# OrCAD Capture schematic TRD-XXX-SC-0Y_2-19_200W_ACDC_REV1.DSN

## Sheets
1 4: size A3
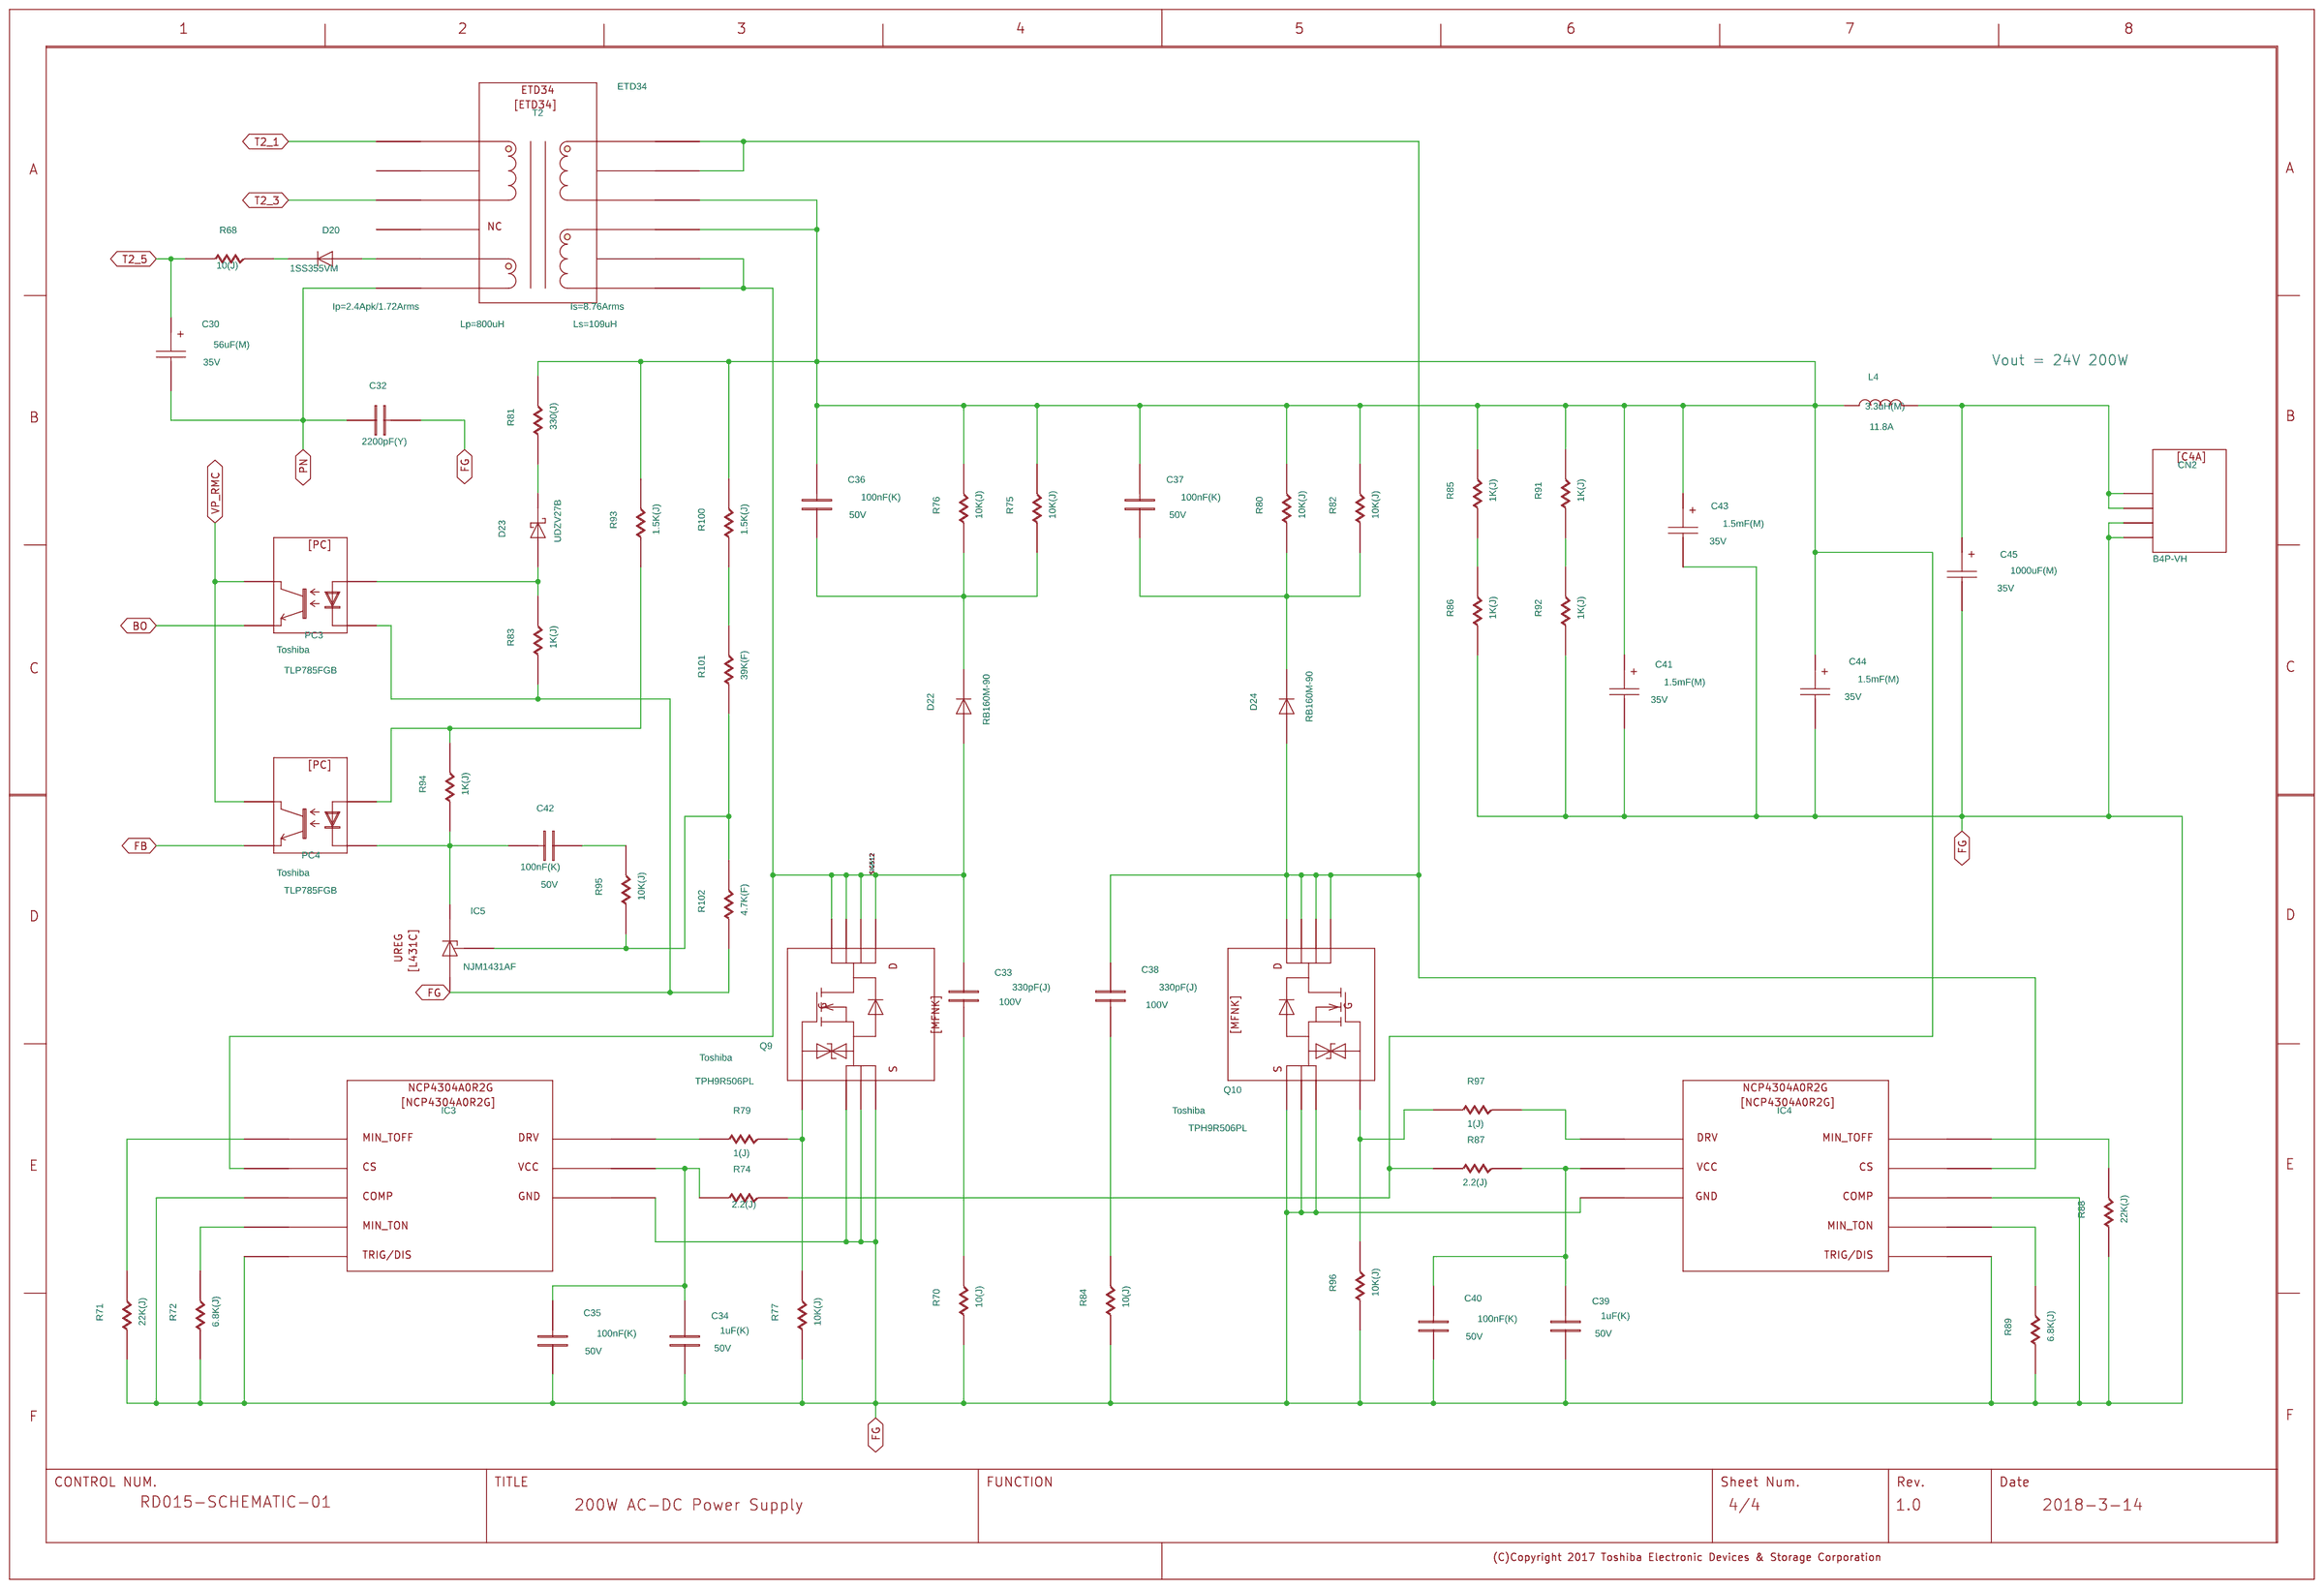
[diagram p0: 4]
2 3: size A3
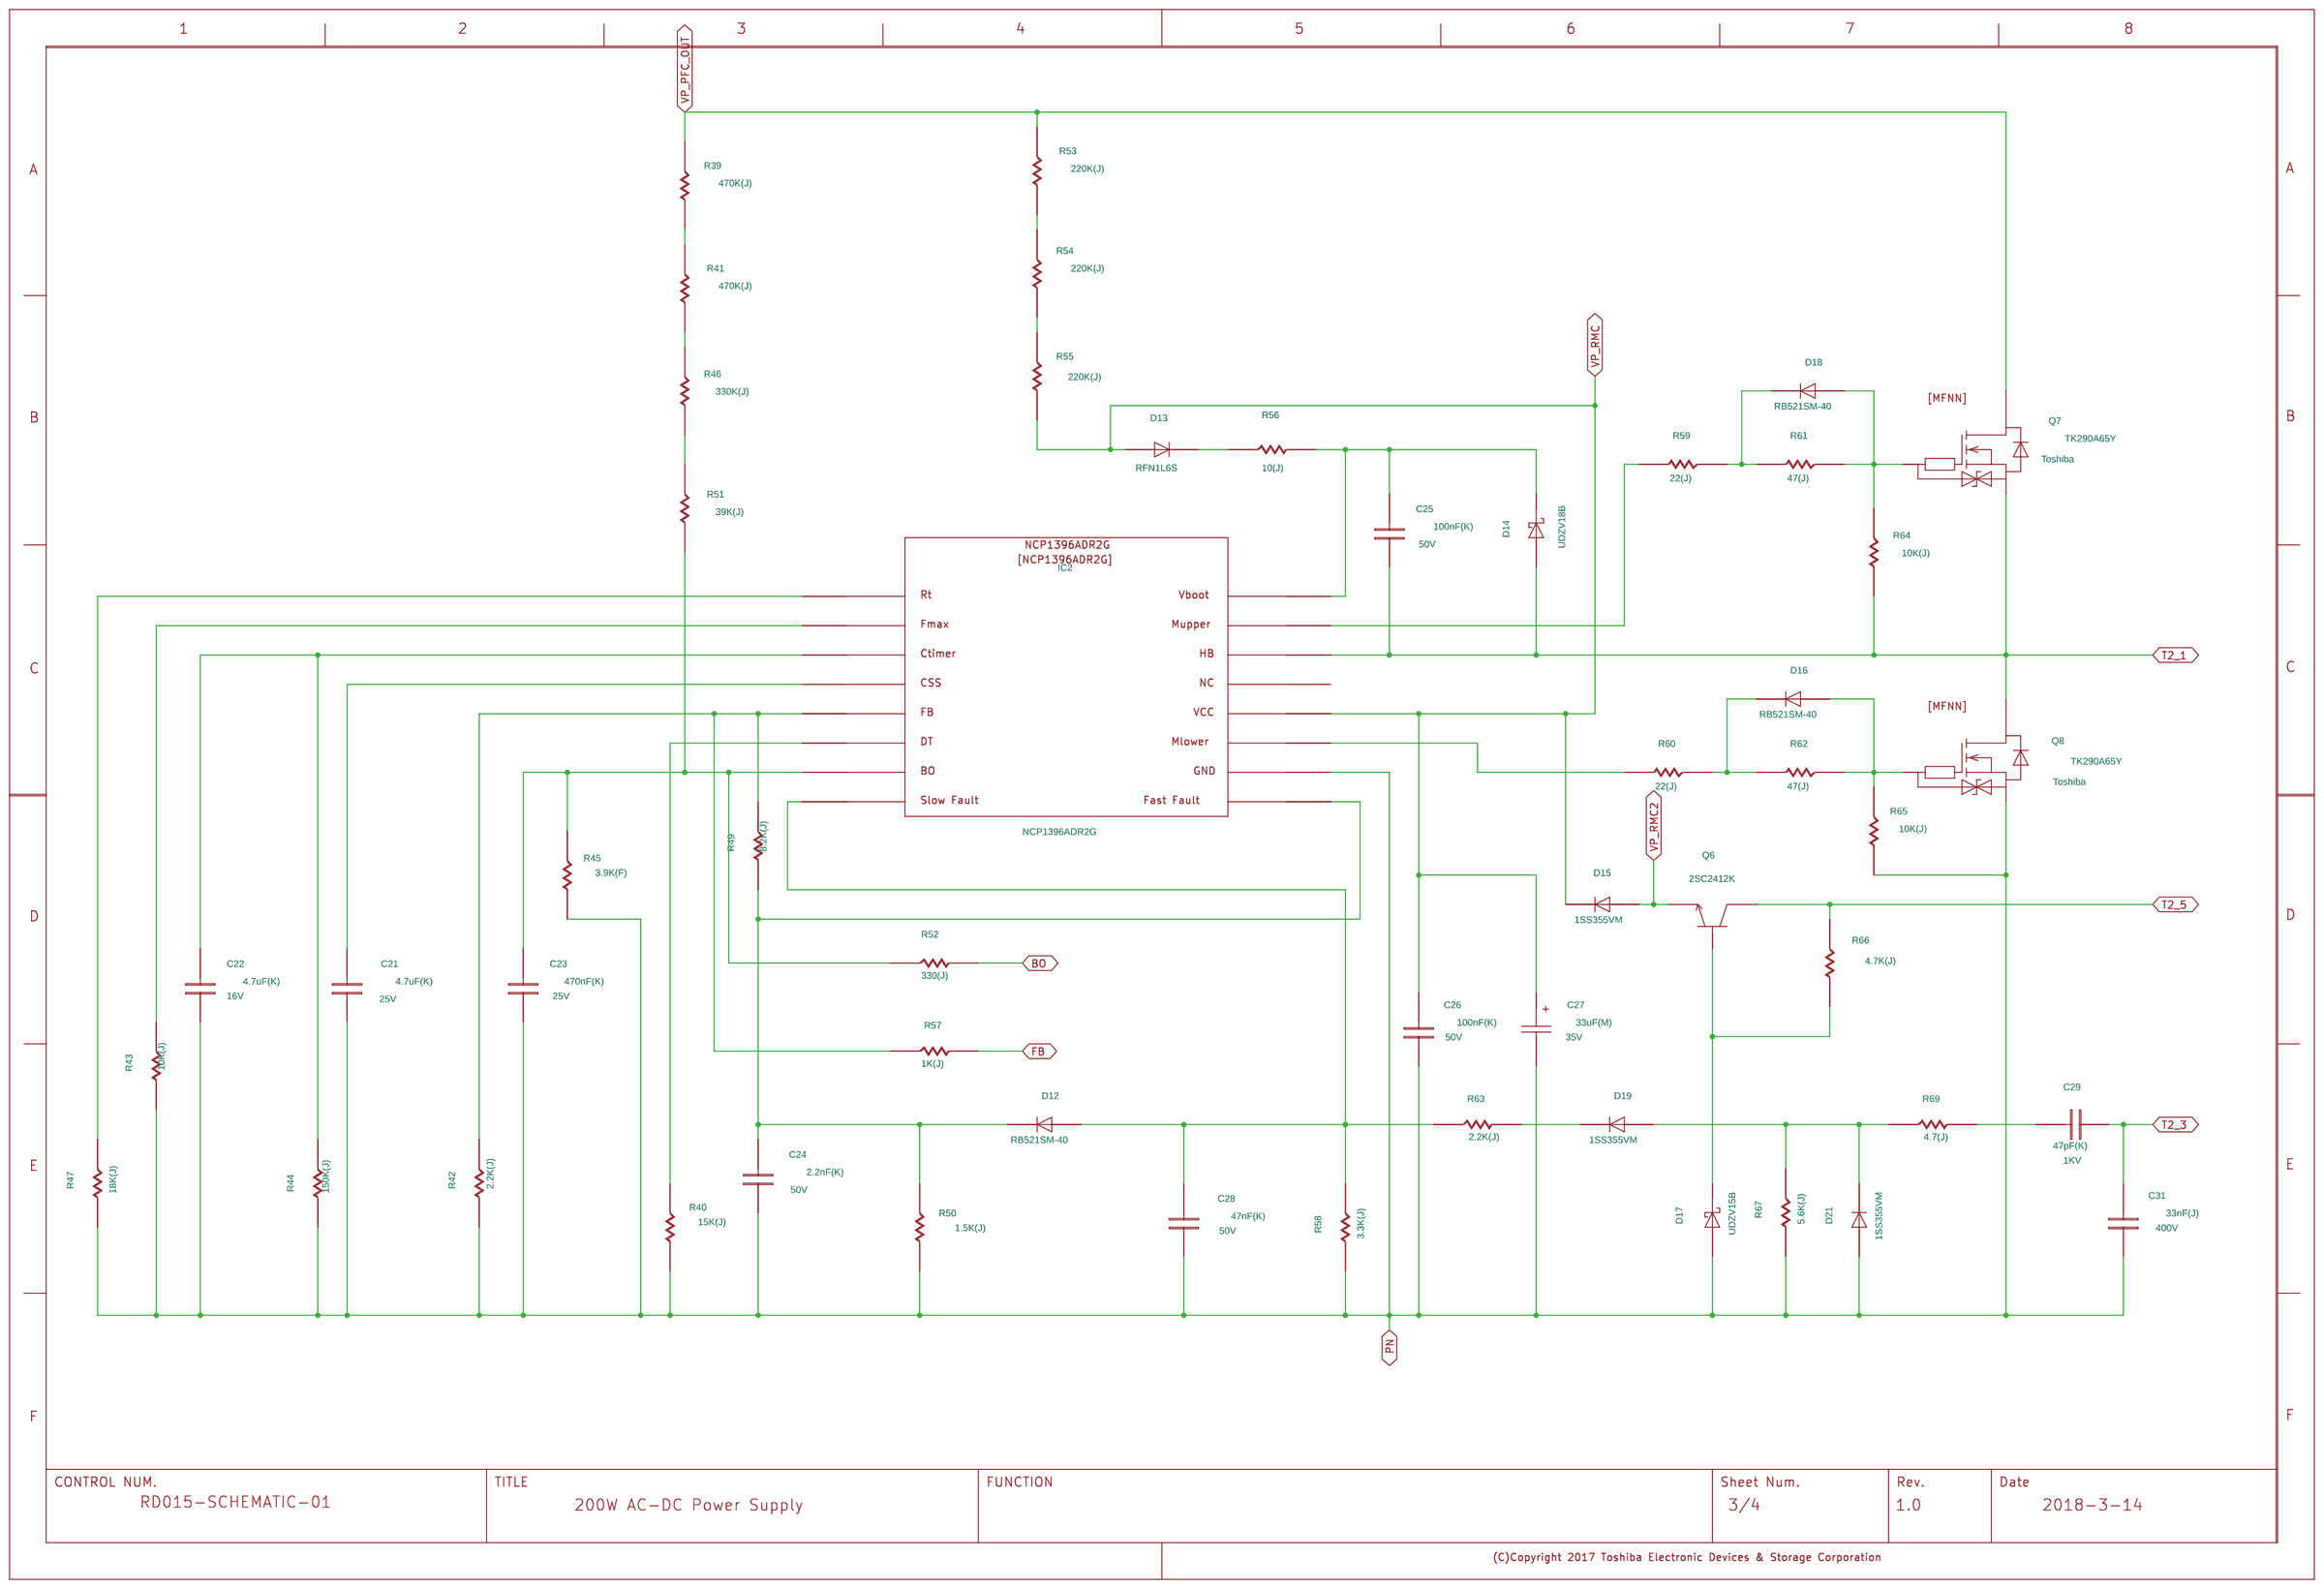
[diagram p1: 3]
3 2: size A3
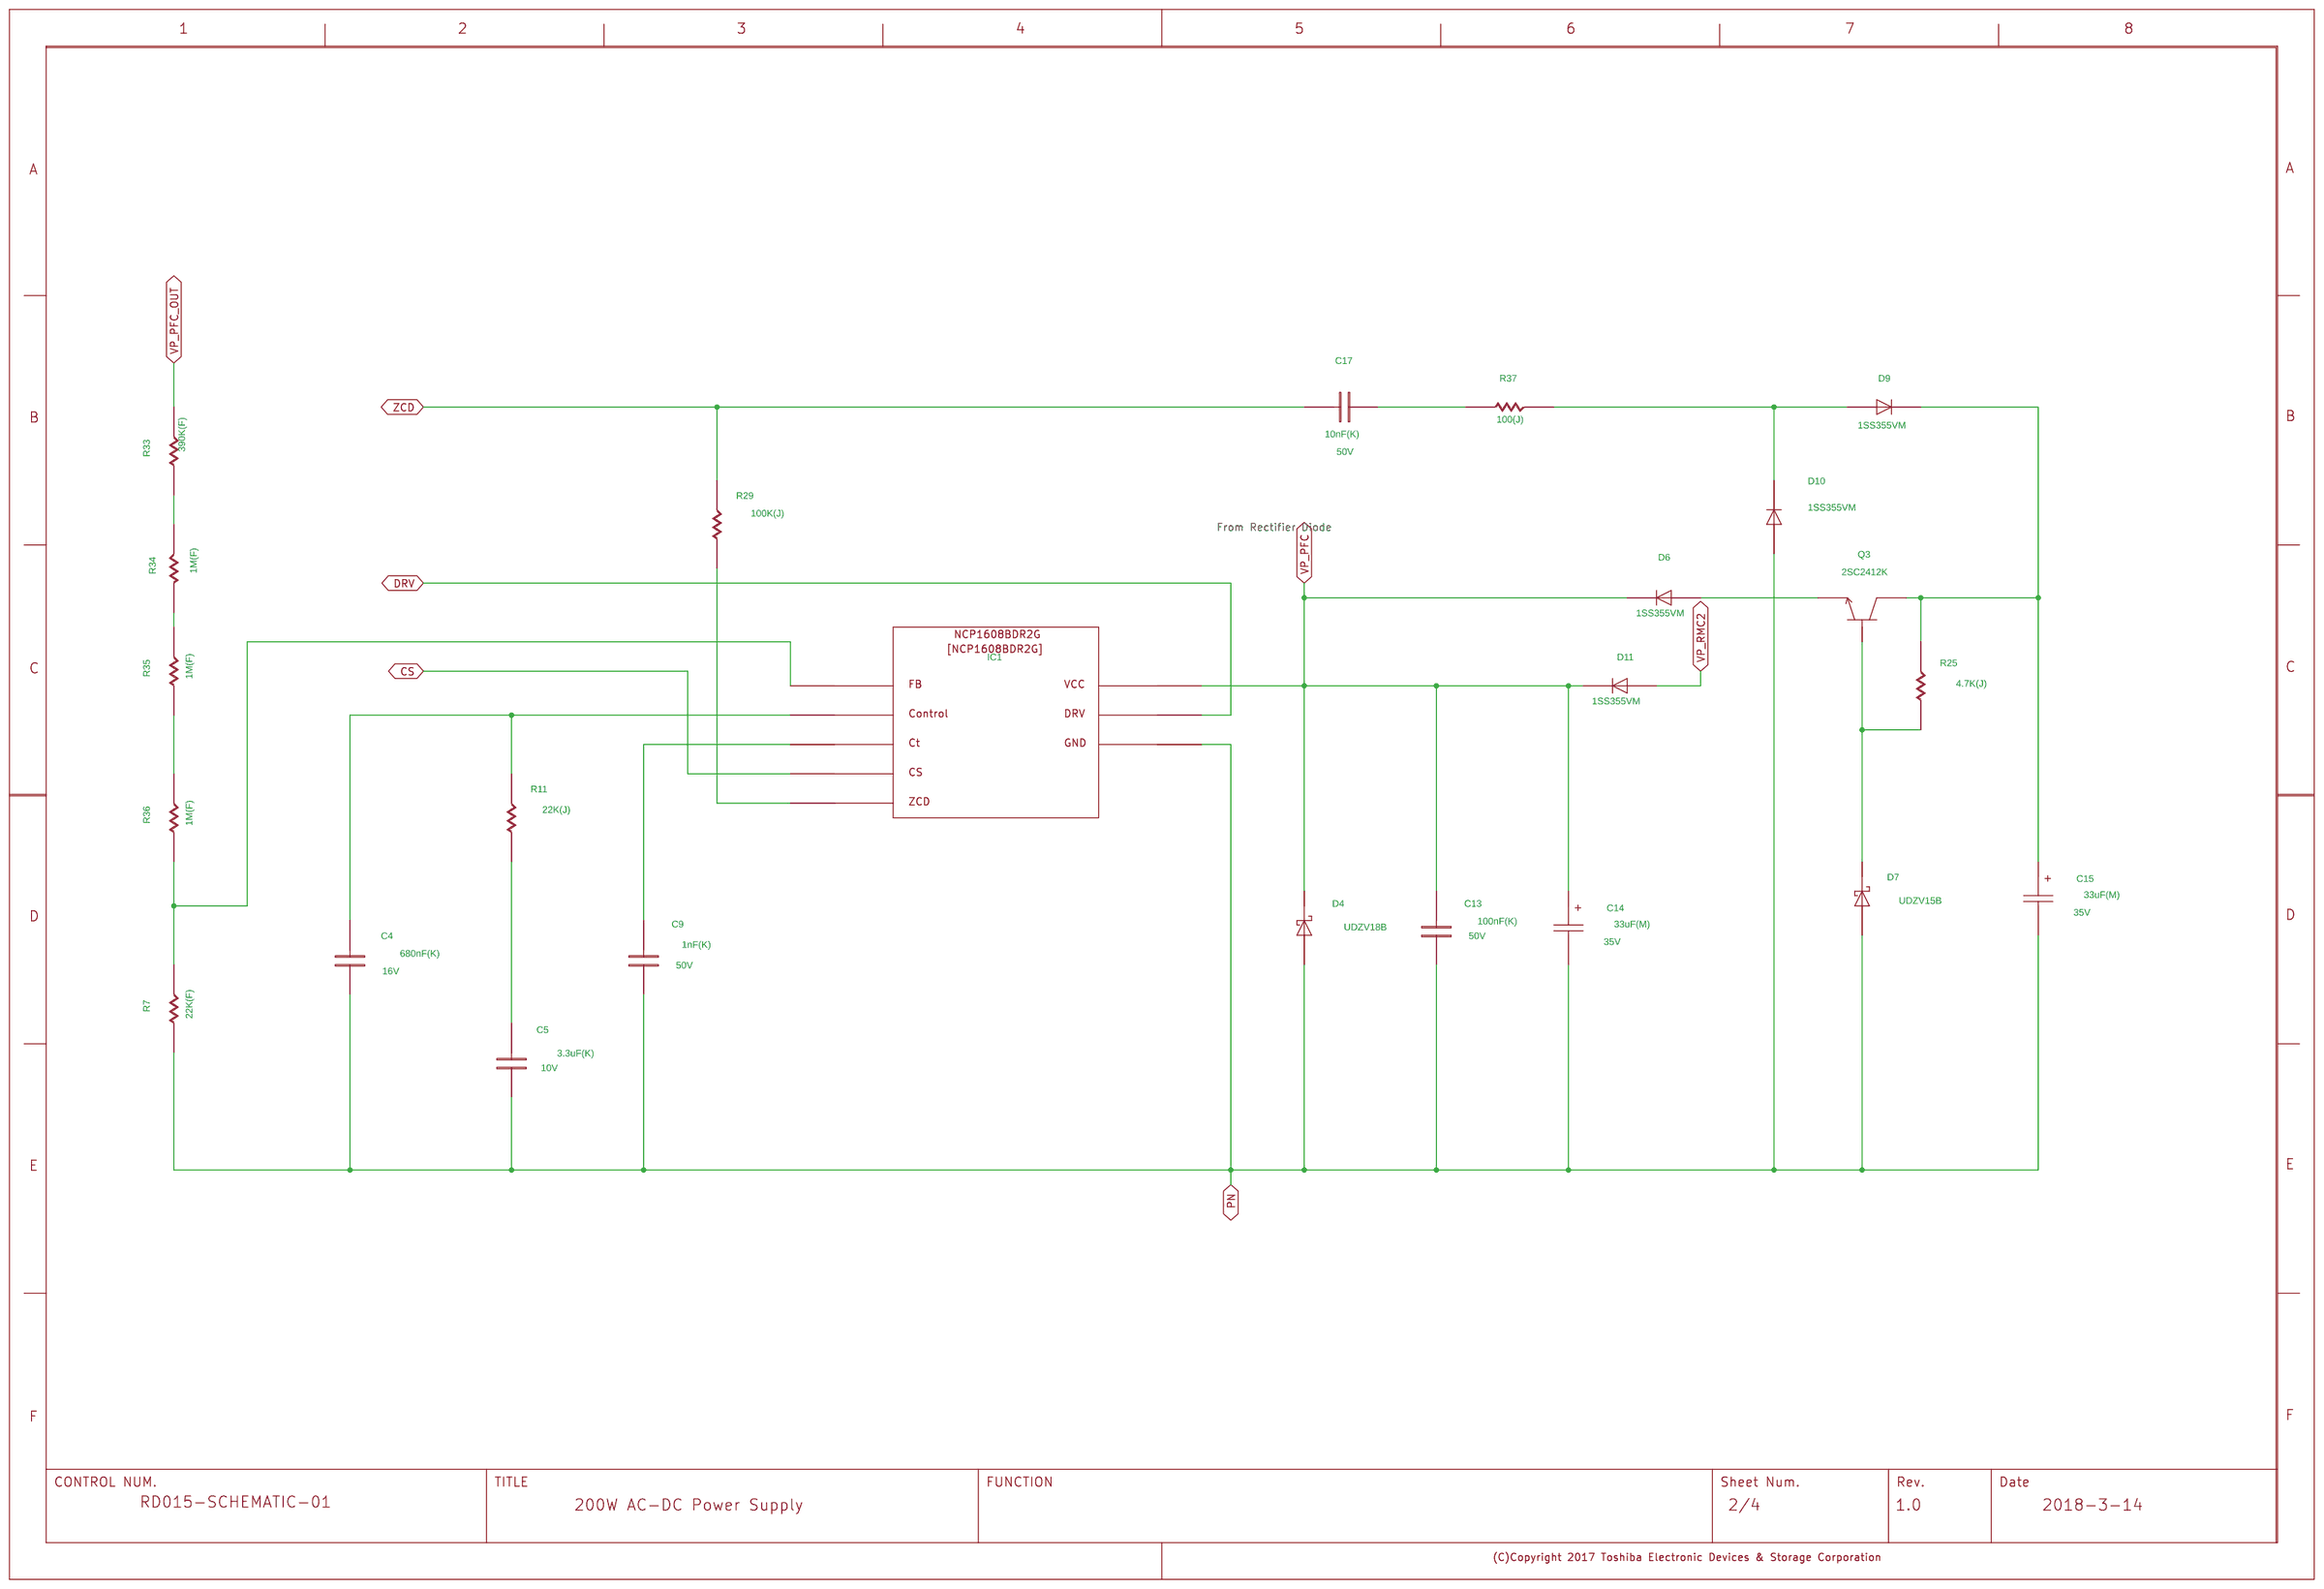
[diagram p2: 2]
4 1: size A3
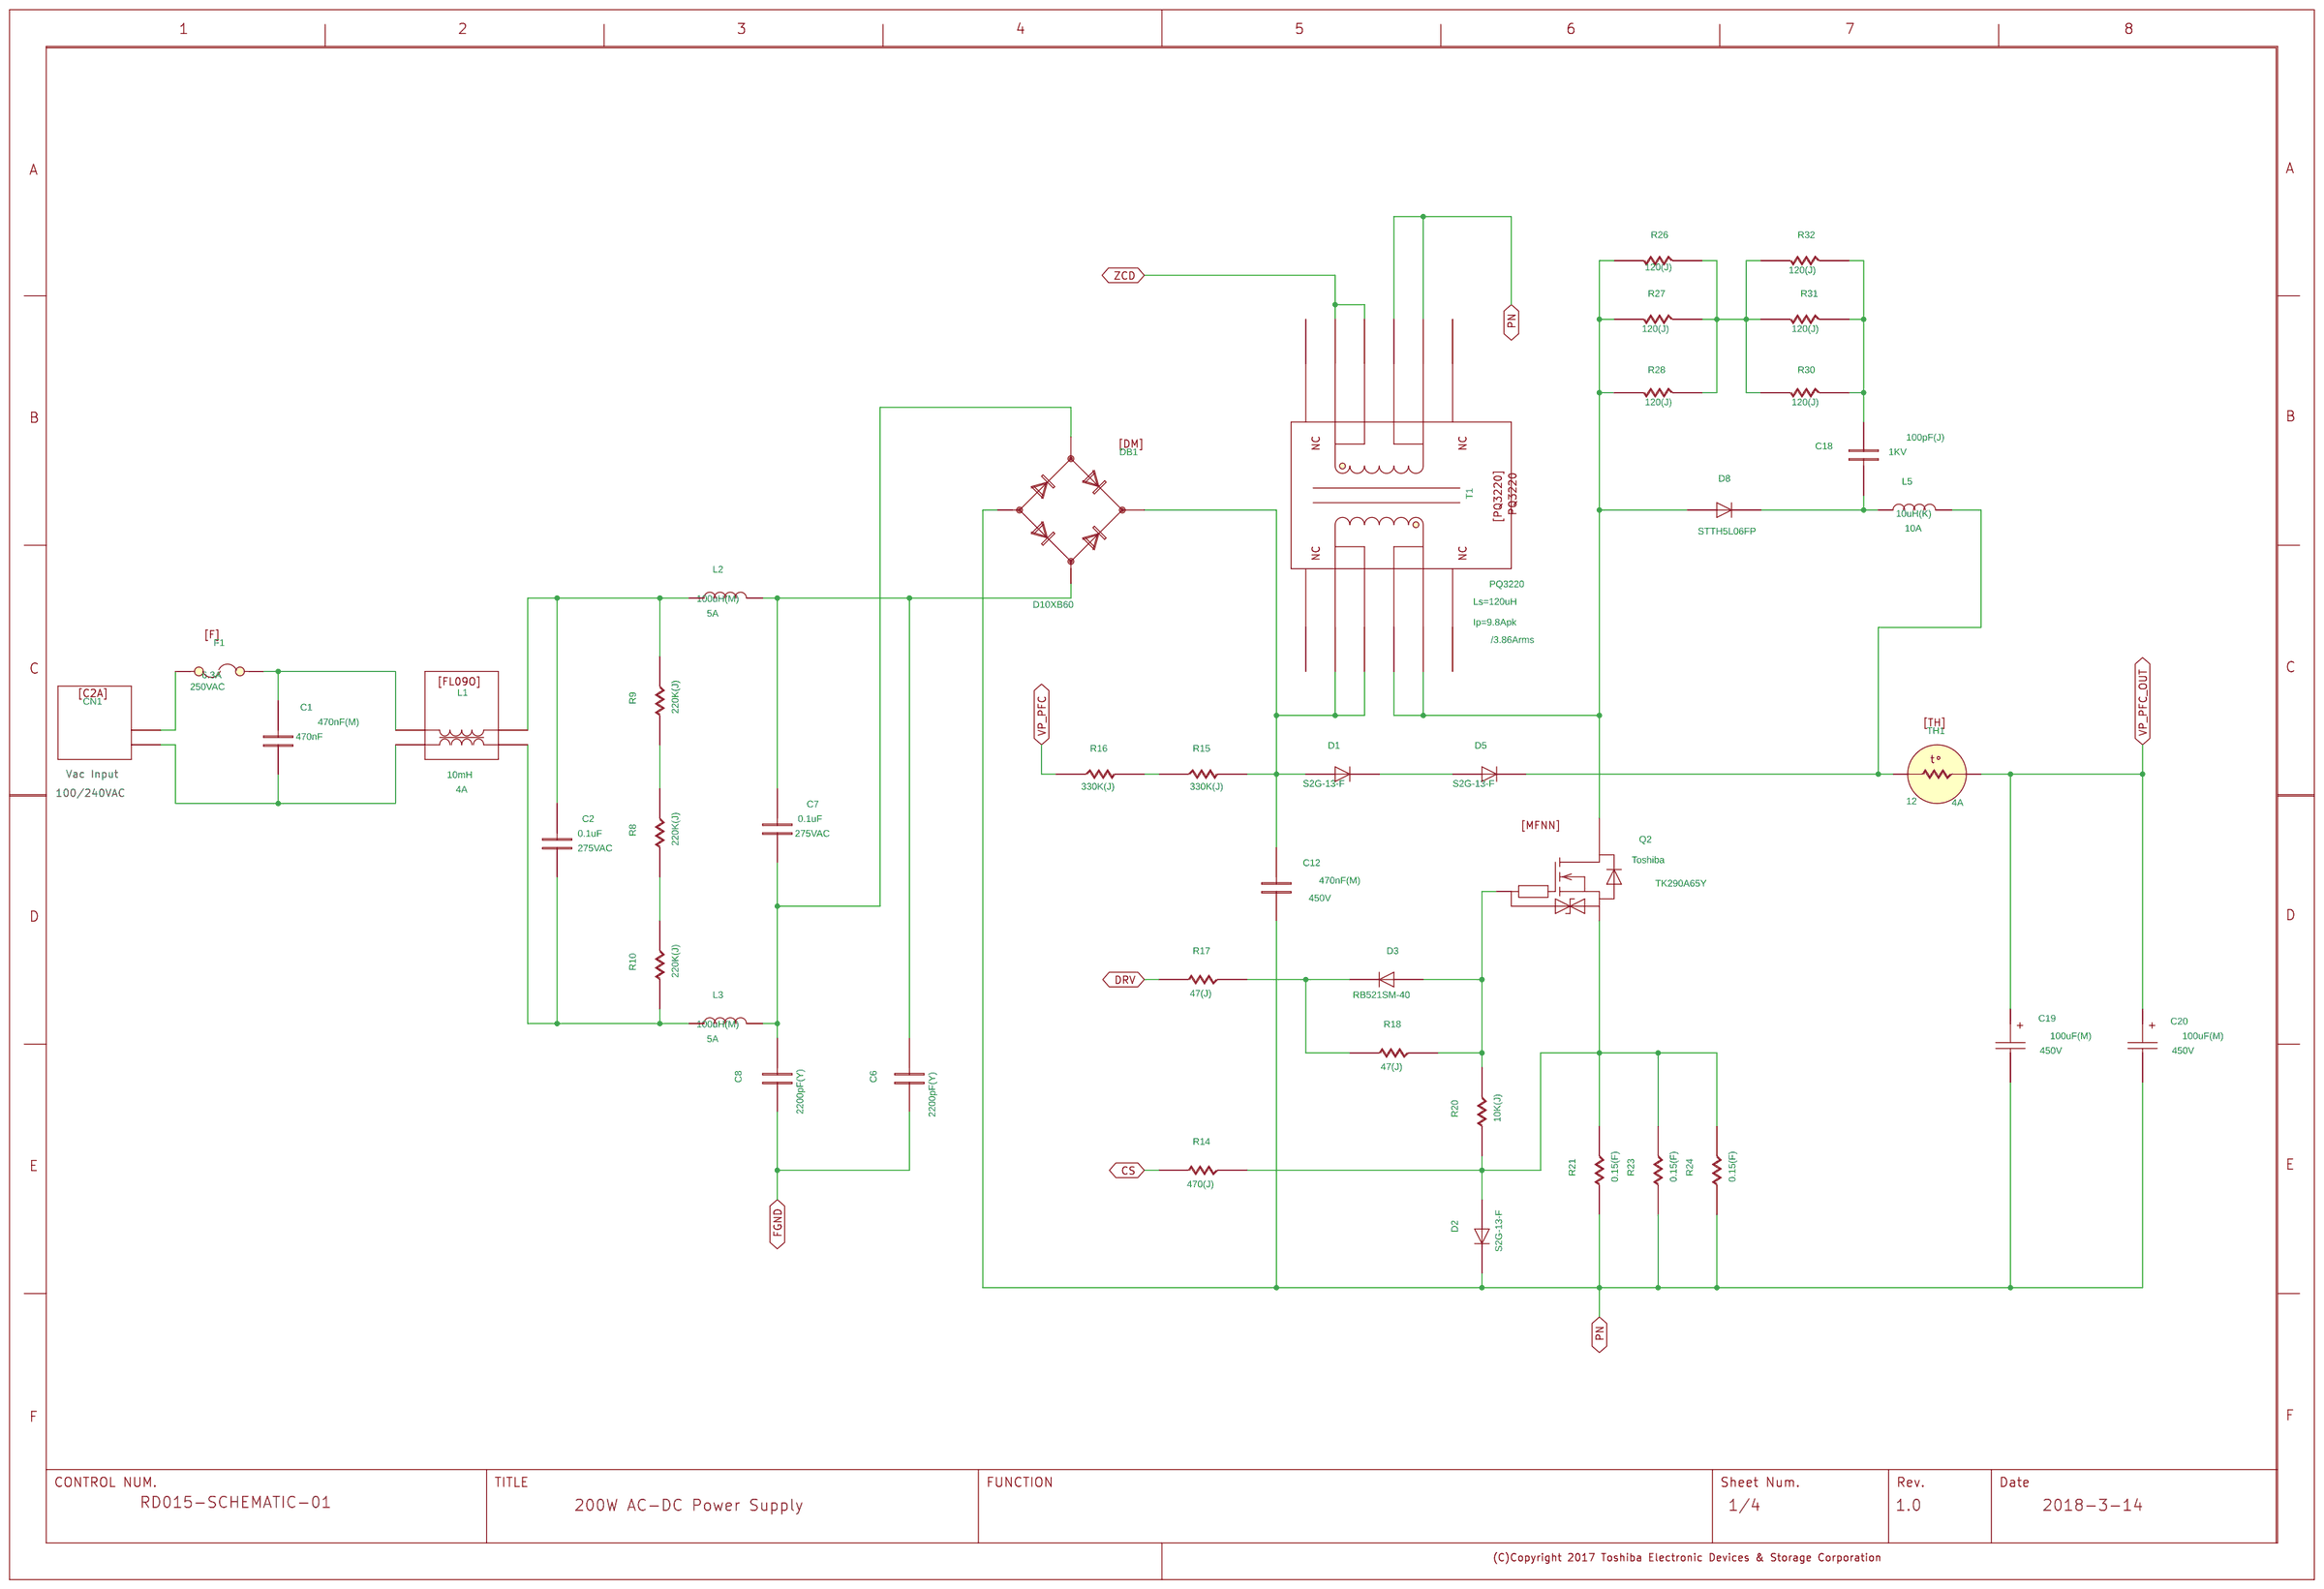
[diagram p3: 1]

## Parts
sheet 1
C1  C  [DIP]
C2  C  [DIP]
C6  C  [DIP]
C7  C  [DIP]
C8  C  [DIP]
C12  C  [DIP]
C18  C  [DIP]
C19  CP  [DIP]
C20  CP  [DIP]
CN1  C2A
D1  D  [SMB]
D2  D  [SMB]
D3  D  [EMD2]
D5  D  [SMB]
D8  D  [TO-220FPAC]
DB1  DM  [SIP]
F1  F  [DIP]
L1  FL09O  [DIP]
L2  L  [DIP]
L3  L  [DIP]
L5  L  [DIP]
Q2  MFNN  [TO-220SIS]
R8  R  [3216]
R9  R  [3216]
R10  R  [3216]
R14  R  [1608]
R15  R  [3216]
R16  R  [3216]
R17  R  [3216]
R18  R  [3216]
R20  R  [1608]
R21  R  [3226]
R23  R  [3226]
R24  R  [3226]
R26  R  [3216]
R27  R  [3216]
R28  R  [3216]
R30  R  [3216]
R31  R  [3216]
R32  R  [3216]
T1  S-PQ3220  [DIP]
TH1  TH  [DIP]
U?#3  WAKU_DEF100
sheet 2
C4  C  [2012]
C5  C  [3216]
C9  C  [1608]
C13  C  [1608]
C14  CP  [DIP]
C15  CP  [DIP]
C17  C  [1608]
D4  SBD  [UMD2]
D6  D  [UMD2]
D7  SBD  [UMD2]
D9  D  [UMD2]
D10  D  [UMD2]
D11  D  [UMD2]
IC1  S-NCP1608BDR2G  [SOIC]
Q3  TRN  [SOT-346]
R7  R  [1608]
R11  R  [1608]
R25  R  [1608]
R29  R  [1608]
R33  R  [1608]
R34  R  [1608]
R35  R  [1608]
R36  R  [1608]
R37  R  [3216]
U?#2  WAKU_DEF100
sheet 3
C21  C  [3216]
C22  C  [3216]
C23  C  [2012]
C24  C  [1608]
C25  C  [1608]
C26  C  [1608]
C27  CP  [DIP]
C28  C  [1608]
C29  C  [3216]
C31  C  [DIP]
D12  D  [EMD2]
D13  D  [PMDS]
D14  SBD  [UMD2]
D15  D  [UMD2]
D16  D  [EMD2]
D17  SBD  [UMD2]
D18  D  [EMD2]
D19  D  [UMD2]
D21  D  [UMD2]
IC2  S-NCP1396ADR2G  [SOIC]
Q6  TRN  [SOT-346]
Q7  MFNN  [TO-346]
Q8  MFNN  [TO-346]
R39  R  [3216]
R40  R  [1608]
R41  R  [3216]
R42  R  [1608]
R43  R  [1608]
R44  R  [1608]
R45  R  [1608]
R46  R  [3216]
R47  R  [1608]
R49  R  [1608]
R50  R  [1608]
R51  R  [1608]
R52  R  [1608]
R53  R  [3216]
R54  R  [3216]
R55  R  [3216]
R56  R  [1608]
R57  R  [1608]
R58  R  [1608]
R59  R  [3216]
R60  R  [3216]
R61  R  [3216]
R62  R  [3216]
R63  R  [1608]
R64  R  [1608]
R65  R  [1608]
R66  R  [1608]
R67  R  [1608]
R69  R  [1608]
U?#1  WAKU_DEF100
sheet 4
C30  CP  [DIP]
C32  C  [DIP]
C33  C  [1608]
C34  C  [3216]
C35  C  [1608]
C36  C  [1608]
C37  C  [1608]
C38  C  [1608]
C39  C  [3216]
C40  C  [1608]
C41  CP  [DIP]
C42  C  [1608]
C43  CP  [DIP]
C44  CP  [DIP]
C45  CP  [DIP]
CN2  C4A
D20  D  [UMD2]
D22  D  [PMDU]
D23  SBD  [UMD2]
D24  D  [PMDU]
IC3  S-NCP4304A0R2G  [SOIC]
IC4  S-NCP4304A0R2G  [SOIC]
IC5  L431C  [SOT-23]
L4  L  [DIP]
PC3  PC  [DIP4]
PC4  PC  [DIP4]
Q9  MFNK  [SOP Advance]
Q10  MFNK  [SOP Advance]
R68  R  [1608]
R70  R  [3216]
R71  R  [1608]
R72  R  [1608]
R74  R  [1608]
R75  R  [3216]
R76  R  [3216]
R77  R  [1608]
R79  R  [1608]
R80  R  [3216]
R81  R  [1608]
R82  R  [3216]
R83  R  [1608]
R84  R  [3216]
R85  R  [3216]
R86  R  [3216]
R87  R  [1608]
R88  R  [1608]
R89  R  [1608]
R91  R  [3216]
R92  R  [3216]
R93  R  [1608]
R94  R  [1608]
R95  R  [1608]
R96  R  [1608]
R97  R  [1608]
R100  R  [1608]
R101  R  [1608]
R102  R  [1608]
T2  S-ETD34
U?#4  WAKU_DEF100

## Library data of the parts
C1 = C: COMPONENTTYPE: 4; GCOUNT: 1; MAXGCOUNT: 1; USERCOMPTEXT1: 470nF; USERCOMPTEXT2: 275VAC; VAL1: 470nF(M); VAL2: 275VAC; VAL3: ECQU2A474ML
C2 = C: COMPONENTTYPE: 4; GCOUNT: 1; MAXGCOUNT: 1; USERCOMPTEXT1: 0.1uF; USERCOMPTEXT2: 275VAC; VAL1: 0.1uF(M); VAL2: 275VAC; VAL3: ECQUAAF104ML
C6 = C: COMPONENTTYPE: 4; GCOUNT: 1; MAXGCOUNT: 1; USERCOMPTEXT1: 2200pF(Y); VAL1: 2.2nF(K); VAL2: 250VAC; VAL3: DE1E3KX222MA5BA01
C7 = C: COMPONENTTYPE: 4; GCOUNT: 1; MAXGCOUNT: 1; USERCOMPTEXT1: 0.1uF; USERCOMPTEXT2: 275VAC; VAL1: 0.1uF; VAL2: 275VAC; VAL3: ECQUAAF104ML
C8 = C: COMPONENTTYPE: 4; GCOUNT: 1; MAXGCOUNT: 1; USERCOMPTEXT1: 2200pF(Y); VAL1: 2.2nF(K); VAL2: 10V; VAL3: DE1E3KX222MA5BA01
C12 = C: COMPONENTTYPE: 4; GCOUNT: 1; MAXGCOUNT: 1; VAL1: 470nF(M); VAL2: 450V; VAL3: ECW2W474JAQ
C18 = C: COMPONENTTYPE: 4; GCOUNT: 1; MAXGCOUNT: 1; VAL1: 100pF(J); VAL2: 1KV; VAL3: DEA1X3A101JN2A
C19 C20 = CP: COMPONENTTYPE: 4; GCOUNT: 1; MAXGCOUNT: 1; OUMEPARTTYPE: C; VAL1: 100uF(M); VAL2: 450V; VAL3: EKXL451ELL101MMP1S
CN1 = C2A: COMPONENTTYPE: 4; GCOUNT: 1; MAXGCOUNT: 1; OUMEPARTTYPE: CN; VAL3: B2P3-VH
D1 D5 = D: COMPONENTTYPE: 4; GCOUNT: 1; MAXGCOUNT: 1; USERCOMPTEXT1: S2G-13-F; VAL1: S2G-13-F; VAL3: S2G-13-F
D2 = D: COMPONENTTYPE: 4; GCOUNT: 1; MAXGCOUNT: 1; VAL1: S2G-13-F; VAL3: S2G-13-F
D3 D12 D16 D18 = D: COMPONENTTYPE: 4; GCOUNT: 1; MAXGCOUNT: 1; VAL1: RB521SM-40; VAL3: RB521SM-40
D8 = D: COMPONENTTYPE: 4; GCOUNT: 1; MAXGCOUNT: 1; VAL1: STTH5L06FP; VAL3: STTH5L06FP
DB1 = DM: COMPONENTTYPE: 4; GCOUNT: 1; MAXGCOUNT: 1; OUMEPARTTYPE: D; USERCOMPTEXT1: D10XB60; VAL1: D10XB60; VAL3: D10XB60
F1 = F: COMPONENTTYPE: 4; GCOUNT: 1; MAXGCOUNT: 1; USERCOMPTEXT1: 250VAC; USERCOMPTEXT2: 6.3A; VAL1: 6.3A; VAL3: 021506.3
L1 = FL09O: COMPONENTTYPE: 4; GCOUNT: 1; MAXGCOUNT: 1; OUMEPARTTYPE: FL; VAL1: 10mH; VAL2: 4A; VAL3: HNC-SHP0.5-S
L2 L3 = L: COMPONENTTYPE: 4; GCOUNT: 1; MAXGCOUNT: 1; USERCOMPTEXT1: 5A; VAL1: 100uH(M); VAL2: 890mA; VAL3: AFP20H-4A100S
L5 = L: COMPONENTTYPE: 4; GCOUNT: 1; MAXGCOUNT: 1; VAL1: 10uH(K); VAL2: 10A; VAL3: BL01RN1A1F1J
Q2 Q7 Q8 = MFNN: COMPONENTTYPE: 4; GCOUNT: 1; MAXGCOUNT: 1; OUMEPARTTYPE: Q; USERCOMPTEXT1: Toshiba; VAL1: TK290A65Y; VAL3: TK290A65Y
R8-R10 R53-R55 = R: COMPONENTTYPE: 4; GCOUNT: 1; MAXGCOUNT: 1; VAL1: 220K(J); VAL2: 250mW
R14 = R: COMPONENTTYPE: 4; GCOUNT: 1; MAXGCOUNT: 1; VAL1: 470(J); VAL2: 100mW
R15 R16 = R: COMPONENTTYPE: 4; GCOUNT: 1; MAXGCOUNT: 1; VAL1: 330K(J); VAL2: 250mW
R17 R18 R61 R62 = R: COMPONENTTYPE: 4; GCOUNT: 1; MAXGCOUNT: 1; VAL1: 47(J); VAL2: 250mW
R20 R77 R95 R96 = R: COMPONENTTYPE: 4; GCOUNT: 1; MAXGCOUNT: 1; VAL1: 10K(J); VAL2: 100mW
R21 R23 R24 = R: COMPONENTTYPE: 4; GCOUNT: 1; MAXGCOUNT: 1; VAL1: 0.15(F); VAL2: 500mW
R26-R28 R30-R32 = R: COMPONENTTYPE: 4; GCOUNT: 1; MAXGCOUNT: 1; VAL1: 120(J); VAL2: 250mW
T1 = S-PQ3220: COMPONENTTYPE: 4; USERCOMPTEXT1: Ls=120uH; USERCOMPTEXT2: Ip=9.8Apk; USERCOMPTEXT3: /3.86Arms; VAL1: PQ3220
TH1 = TH: COMPONENTTYPE: 4; GCOUNT: 1; MAXGCOUNT: 1; OUMEPARTTYPE: MT; VAL1: 12; VAL2: 4A; VAL3: B57211P120M301
U?#3 = WAKU_DEF100: COMPONENTTYPE: 2; DATE: 2018-3-14; DRAWINGNUMBER: RD015-SCHEMATIC-01; FUNCTION: Rectification Circuit; PAGENUMBER: 001; REVISION: 1.0; SAVEAREA0: -45080,-4508,463680,3046592; SHEETNUMBER: 1/4; TITLE: 200W AC-DC Power Supply; UPDATEDATE: 2018/03/14; UPDATETIME: 17:07:09; UPDATEUSER: d5009410
C4 = C: COMPONENTTYPE: 4; GCOUNT: 1; MAXGCOUNT: 1; VAL1: 680nF(K); VAL2: 16V
C5 = C: COMPONENTTYPE: 4; GCOUNT: 1; MAXGCOUNT: 1; VAL1: 3.3uF(K); VAL2: 10V
C9 = C: COMPONENTTYPE: 4; GCOUNT: 1; MAXGCOUNT: 1; VAL1: 1nF(K); VAL2: 50V
C13 C25 C26 C35-C37 C40 C42 = C: COMPONENTTYPE: 4; GCOUNT: 1; MAXGCOUNT: 1; VAL1: 100nF(K); VAL2: 50V
C14 C15 C27 = CP: COMPONENTTYPE: 4; GCOUNT: 1; MAXGCOUNT: 1; OUMEPARTTYPE: C; VAL1: 33uF(M); VAL2: 35V; VAL3: EKY-350ELL330ME110
C17 = C: COMPONENTTYPE: 4; GCOUNT: 1; MAXGCOUNT: 1; VAL1: 10nF(K); VAL2: 50V
D4 D14 = SBD: COMPONENTTYPE: 4; GCOUNT: 1; MAXGCOUNT: 1; OUMEPARTTYPE: D; VAL1: UDZV18B; VAL3: UDZV18B
D6 D9-D11 D15 D19-D21 = D: COMPONENTTYPE: 4; GCOUNT: 1; MAXGCOUNT: 1; VAL1: 1SS355VM; VAL3: 1SS355VM
D7 D17 = SBD: COMPONENTTYPE: 4; GCOUNT: 1; MAXGCOUNT: 1; OUMEPARTTYPE: D; VAL1: UDZV15B; VAL3: UDZV15B
IC1 = S-NCP1608BDR2G: COMPONENTTYPE: 4; VAL1: NCP1608BDR2G; VAL3: NCP1608BDR2G
Q3 Q6 = TRN: COMPONENTTYPE: 4; GCOUNT: 1; MAXGCOUNT: 1; OUMEPARTTYPE: Q; VAL1: 2SC2412K; VAL3: 2SC2412K
R7 = R: COMPONENTTYPE: 4; GCOUNT: 1; MAXGCOUNT: 1; VAL1: 22K(F); VAL2: 100mW
R11 R71 R88 = R: COMPONENTTYPE: 4; GCOUNT: 1; MAXGCOUNT: 1; VAL1: 22K(J); VAL2: 100mW
R25 = R: COMPONENTTYPE: 4; GCOUNT: 1; MAXGCOUNT: 1; VAL1: 4.7K(J); VAL2: 100mW
R29 = R: COMPONENTTYPE: 4; GCOUNT: 1; MAXGCOUNT: 1; VAL1: 100K(J); VAL2: 100mW
R33 = R: COMPONENTTYPE: 4; GCOUNT: 1; MAXGCOUNT: 1; VAL1: 390K(F); VAL2: 100mW
R34-R36 = R: COMPONENTTYPE: 4; GCOUNT: 1; MAXGCOUNT: 1; VAL1: 1M(F); VAL2: 100mW
R37 = R: COMPONENTTYPE: 4; GCOUNT: 1; MAXGCOUNT: 1; VAL1: 100(J); VAL2: 250mW
U?#2 = WAKU_DEF100: AUTHOR: g4302510; COMPONENTTYPE: 2; DATE: 2018-3-14; DRAWINGNUMBER: RD015-SCHEMATIC-01; FUNCTION: PFC Controller; PAGENUMBER: 002; REVISION: 1.0; SAVEAREA0: -45080,-4508,463680,304612; SHEETNUMBER: 2/4; TIME: 19:37:43; TITLE: 200W AC-DC Power Supply; UPDATEDATE: 2018/03/14; UPDATETIME: 17:07:10; UPDATEUSER: d5009410
C21 = C: COMPONENTTYPE: 4; GCOUNT: 1; MAXGCOUNT: 1; VAL1: 4.7uF(K); VAL2: 25V
C22 = C: COMPONENTTYPE: 4; GCOUNT: 1; MAXGCOUNT: 1; VAL1: 4.7uF(K); VAL2: 16V
C23 = C: COMPONENTTYPE: 4; GCOUNT: 1; MAXGCOUNT: 1; VAL1: 470nF(K); VAL2: 25V
C24 = C: COMPONENTTYPE: 4; GCOUNT: 1; MAXGCOUNT: 1; VAL1: 2.2nF(K); VAL2: 50V
C28 = C: COMPONENTTYPE: 4; GCOUNT: 1; MAXGCOUNT: 1; VAL1: 47nF(K); VAL2: 50V
C29 = C: COMPONENTTYPE: 4; GCOUNT: 1; MAXGCOUNT: 1; VAL1: 47pF(K); VAL2: 1KV
C31 = C: COMPONENTTYPE: 4; GCOUNT: 1; MAXGCOUNT: 1; VAL1: 33nF(J); VAL2: 400V; VAL3: ECWF4333JL
D13 = D: COMPONENTTYPE: 4; GCOUNT: 1; MAXGCOUNT: 1; VAL1: RFN1L6S; VAL3: RFN1L6S
IC2 = S-NCP1396ADR2G: COMPONENTTYPE: 4; VAL1: NCP1396ADR2G; VAL3: NCP1396ADR2G
R39 R41 = R: COMPONENTTYPE: 4; GCOUNT: 1; MAXGCOUNT: 1; VAL1: 470K(J); VAL2: 250mW; VAL3: ERDS2TJ474V
R40 = R: COMPONENTTYPE: 4; GCOUNT: 1; MAXGCOUNT: 1; VAL1: 15K(J); VAL2: 100mW; VAL3: ERJ6GEYJ153V
R42 = R: COMPONENTTYPE: 4; GCOUNT: 1; MAXGCOUNT: 1; VAL1: 2.2K(J); VAL2: 100mW
R43 R64 R65 = R: COMPONENTTYPE: 4; GCOUNT: 1; MAXGCOUNT: 1; VAL1: 10K(J); VAL2: 100mW; VAL3: RK73B1JTTD103J@@
R44 = R: COMPONENTTYPE: 4; GCOUNT: 1; MAXGCOUNT: 1; VAL1: 150K(J); VAL2: 100mW; VAL3: ERJ6GEYJ154V
R45 = R: COMPONENTTYPE: 4; GCOUNT: 1; MAXGCOUNT: 1; VAL1: 3.9K(F); VAL2: 100mW; VAL3: ERJ6GEYJ153V
R46 = R: COMPONENTTYPE: 4; GCOUNT: 1; MAXGCOUNT: 1; VAL1: 330K(J); VAL2: 250mW; VAL3: RK73H2ETE334F
R47 = R: COMPONENTTYPE: 4; GCOUNT: 1; MAXGCOUNT: 1; VAL1: 18K(J); VAL2: 100mW
R49 = R: COMPONENTTYPE: 4; GCOUNT: 1; MAXGCOUNT: 1; VAL1: 8.2K(J); VAL2: 100mW; VAL3: ERJ6GEYJ393V
R50 R93 R100 = R: COMPONENTTYPE: 4; GCOUNT: 1; MAXGCOUNT: 1; VAL1: 1.5K(J); VAL2: 100mW
R51 = R: COMPONENTTYPE: 4; GCOUNT: 1; MAXGCOUNT: 1; VAL1: 39K(J); VAL2: 100mW; VAL3: ERJ6GEYJ393V
R52 = R: COMPONENTTYPE: 4; GCOUNT: 1; MAXGCOUNT: 1; VAL1: 330(J); VAL2: 100mW; VAL3: ERJ6GEYJ332V
R56 = R: COMPONENTTYPE: 4; GCOUNT: 1; MAXGCOUNT: 1; VAL1: 10(J); VAL2: 100mW; VAL3: RC0603JR-0710RL
R57 = R: COMPONENTTYPE: 4; GCOUNT: 1; MAXGCOUNT: 1; VAL1: 1K(J); VAL2: 100mW; VAL3: ERJ6GEYJ332V
R58 = R: COMPONENTTYPE: 4; GCOUNT: 1; MAXGCOUNT: 1; VAL1: 3.3K(J); VAL2: 100mW; VAL3: ERJ6GEYJ332V
R59 R60 = R: COMPONENTTYPE: 4; GCOUNT: 1; MAXGCOUNT: 1; VAL1: 22(J); VAL2: 250mW; VAL3: ERJ14YJ220H
R63 = R: COMPONENTTYPE: 4; GCOUNT: 1; MAXGCOUNT: 1; VAL1: 2.2K(J); VAL2: 100mW; VAL3: ERJ6GEYJ332V
R66 = R: COMPONENTTYPE: 4; GCOUNT: 1; MAXGCOUNT: 1; VAL1: 4.7K(J); VAL2: 100mW; VAL3: RK73B1JTTD472J@@
R67 = R: COMPONENTTYPE: 4; GCOUNT: 1; MAXGCOUNT: 1; VAL1: 5.6K(J); VAL2: 100mW; VAL3: ERJ6GEYJ332V
R69 = R: COMPONENTTYPE: 4; GCOUNT: 1; MAXGCOUNT: 1; VAL1: 4.7(J); VAL2: 100mW; VAL3: ERJ6GEYJ332V
U?#1 = WAKU_DEF100: AUTHOR: g4302510; COMPONENTTYPE: 2; DATE: 2018-3-14; DRAWINGNUMBER: RD015-SCHEMATIC-01; FUNCTION: Resonant Mode Controller; PAGENUMBER: 003; REVISION: 1.0; SAVEAREA0: -45080,-4508,463680,304612; SHEETNUMBER: 3/4; TIME: 13:33:42; TITLE: 200W AC-DC Power Supply; UPDATEDATE: 2018/03/14; UPDATETIME: 17:07:10; UPDATEUSER: d5009410
C30 = CP: COMPONENTTYPE: 4; GCOUNT: 1; MAXGCOUNT: 1; OUMEPARTTYPE: C; VAL1: 56uF(M); VAL2: 35V; VAL3: EKY-350ELL560MF110
C32 = C: COMPONENTTYPE: 4; GCOUNT: 1; MAXGCOUNT: 1; VAL1: 2200pF(Y); VAL2: 250VAC; VAL3: DE1E3KX222MA5BA01
C33 C38 = C: COMPONENTTYPE: 4; GCOUNT: 1; MAXGCOUNT: 1; VAL1: 330pF(J); VAL2: 100V
C34 C39 = C: COMPONENTTYPE: 4; GCOUNT: 1; MAXGCOUNT: 1; VAL1: 1uF(K); VAL2: 50V
C41 C43 C44 = CP: COMPONENTTYPE: 4; GCOUNT: 1; MAXGCOUNT: 1; OUMEPARTTYPE: C; VAL1: 1.5mF(M); VAL2: 35V; VAL3: EKY-350ELL152ZMK35S
C45 = CP: COMPONENTTYPE: 4; GCOUNT: 1; MAXGCOUNT: 1; OUMEPARTTYPE: C; VAL1: 1000uF(M); VAL2: 35V; VAL3: EKY-350ELL102MK25S
CN2 = C4A: COMPONENTTYPE: 4; GCOUNT: 1; MAXGCOUNT: 1; OUMEPARTTYPE: CN; VAL3: B4P-VH
D22 D24 = D: COMPONENTTYPE: 4; GCOUNT: 1; MAXGCOUNT: 1; VAL1: RB160M-90; VAL3: RB160M-90
D23 = SBD: COMPONENTTYPE: 4; GCOUNT: 1; MAXGCOUNT: 1; OUMEPARTTYPE: D; VAL1: UDZV27B; VAL3: UDZV27B
IC3 IC4 = S-NCP4304A0R2G: COMPONENTTYPE: 4; VAL1: NCP4304DR2G; VAL3: NCP4304DR2G
IC5 = L431C: COMPONENTTYPE: 4; GCOUNT: 1; MAXGCOUNT: 1; OUMEPARTTYPE: IC; VAL1: NJM1431AF; VAL3: NJM1431AF
L4 = L: COMPONENTTYPE: 4; GCOUNT: 1; MAXGCOUNT: 1; VAL1: 3.3uH(M); VAL2: 11.8A; VAL3: 15332C
PC3 PC4 = PC: COMPONENTTYPE: 4; GCOUNT: 1; MAXGCOUNT: 1; OUMEPARTTYPE: DS; USERCOMPTEXT1: Toshiba; VAL1: TLP785FGB; VAL3: TLP785FGB
Q9 Q10 = MFNK: COMPONENTTYPE: 4; GCOUNT: 1; MAXGCOUNT: 1; OUMEPARTTYPE: Q; USERCOMPTEXT1: Toshiba; VAL1: TPH9R506PL; VAL3: TPH9R506PL
R68 = R: COMPONENTTYPE: 4; GCOUNT: 1; MAXGCOUNT: 1; VAL1: 10(J); VAL2: 100mW
R70 R84 = R: COMPONENTTYPE: 4; GCOUNT: 1; MAXGCOUNT: 1; VAL1: 10(J); VAL2: 250mW
R72 R89 = R: COMPONENTTYPE: 4; GCOUNT: 1; MAXGCOUNT: 1; VAL1: 6.8K(J); VAL2: 100mW
R74 R87 = R: COMPONENTTYPE: 4; GCOUNT: 1; MAXGCOUNT: 1; VAL1: 2.2(J); VAL2: 100mW
R75 R76 R80 R82 = R: COMPONENTTYPE: 4; GCOUNT: 1; MAXGCOUNT: 1; VAL1: 10K(J); VAL2: 250mW
R79 R97 = R: COMPONENTTYPE: 4; GCOUNT: 1; MAXGCOUNT: 1; VAL1: 1(J); VAL2: 100mW
R81 = R: COMPONENTTYPE: 4; GCOUNT: 1; MAXGCOUNT: 1; VAL1: 330(J); VAL2: 100mW
R83 R94 = R: COMPONENTTYPE: 4; GCOUNT: 1; MAXGCOUNT: 1; VAL1: 1K(J); VAL2: 100mW
R85 R86 R91 R92 = R: COMPONENTTYPE: 4; GCOUNT: 1; MAXGCOUNT: 1; VAL1: 1K(J); VAL2: 250mW
R101 = R: COMPONENTTYPE: 4; GCOUNT: 1; MAXGCOUNT: 1; VAL1: 39K(F); VAL2: 100mW
R102 = R: COMPONENTTYPE: 4; GCOUNT: 1; MAXGCOUNT: 1; VAL1: 4.7K(F); VAL2: 100mW
T2 = S-ETD34: COMPONENTTYPE: 4; USERCOMPTEXT1: Ip=2.4Apk/1.72Arms; USERCOMPTEXT2: Is=8.76Arms; VAL1: ETD34; VAL2: Lp=800uH; VAL3: Ls=109uH
U?#4 = WAKU_DEF100: AUTHOR: g4302510; COMPONENTTYPE: 2; DATE: 2018-3-14; DRAWINGNUMBER: RD015-SCHEMATIC-01; FUNCTION: SMPS Controller; PAGENUMBER: 004; REVISION: 1.0; SAVEAREA0: -45080,-4508,463680,304612; SHEETNUMBER: 4/4; TIME: 17:01:22; TITLE: 200W AC-DC Power Supply; UPDATEDATE: 2018/03/14; UPDATETIME: 17:07:10; UPDATEUSER: d5009410

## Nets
BO: PC3.E R52.1
CS: IC1.4 R14.1
DRV: IC1.7 R17.1
FB: PC4.E R57.1
FG: C32.2 C34.1 C35.1 C39.1 C40.1 C41.1 C43.1 C44.1 C45.1 CN2.3 CN2.4 IC3.4 IC3.6 IC3.7 IC4.4 IC4.6 IC4.7 IC5.3 PC3.CA Q9.1 Q9.2 Q9.3 Q10.1 Q10.2 Q10.3 R70.1 R71.1 R72.1 R77.1 R83.1 R84.1 R86.1 R88.1 R89.1 R92.1 R96.1 R102.1
FGND: C6.1 C8.1
PN: C4.1 C5.1 C9.1 C12.1 C13.1 C14.1 C15.1 C19.1 C20.1 C21.1 C22.1 C23.1 C24.1 C26.1 C27.1 C28.1 C30.1 C31.1 C32.1 D2.C D4.A D7.A D10.A D17.A D21.A DB1.M IC1.6 IC2.10 Q8.S R7.1 R21.1 R23.1 R24.1 R40.1 R42.1 R43.1 R44.1 R45.1 R47.1 R50.1 R58.1 R65.1 R67.1 T1.10 T1.11 T2.6
SIG512: C33.1 D22.A IC3.5 Q9.5 Q9.6 Q9.7 Q9.8 T2.7 T2.8
T2_1: C25.1 D14.A IC2.14 Q7.S Q8.D R64.1 T2.1
T2_3: C29.1 C31.2 T2.3
T2_5: C30.2 Q6.C R66.2 R68.1
VP_PFC: C13.2 C14.2 D4.C D6.C D11.C IC1.8 R16.2
VP_PFC_OUT: C19.2 C20.2 Q7.D R33.2 R39.2 R53.2 TH1.2
VP_RMC: C26.2 C27.2 D13.A D15.C IC2.12 PC3.C PC4.C R55.1
VP_RMC2: D11.A D15.A Q6.E
ZCD: C17.2 R29.2 T1.8 T1.9
N00551: R8.1 R10.2
N00555: R8.2 R9.1
N00559: C18.2 D8.C L5.1
N00567: D3.C R17.2 R18.1
N00581: C2.2 L1.2 L2.1 R9.2
N00599: C7.1 C8.2 DB1.AC1 L3.2
N00617: C2.1 L1.4 L3.1 R10.1
N00631: D1.C D5.A
N00635: D8.A Q2.D R26.1 R27.1 R28.1 T1.2 T1.3
N00663: D5.C L5.2 TH1.1
N00689: C18.1 R30.2 R31.2 R32.2
N00715: R15.2 R16.1
N00719: C12.2 D1.A DB1.P R15.1 T1.4 T1.5
N00741: C1.2 F1.2 L1.1
N00763: D3.A Q2.G R18.2 R20.2
N00777: D2.A Q2.S R14.2 R20.1 R21.2 R23.2 R24.2
N00803: C6.2 C7.2 DB1.AC2 L2.2
N00827: CN1.1 F1.1
N00875: C1.1 CN1.2 L1.3
N00889: R26.2 R27.2 R28.2 R30.1 R31.1 R32.1
N01425: C5.2 R11.1
N01429: C4.2 IC1.2 R11.2
N01439: C9.2 IC1.3
N01445: D6.A Q3.E
N01449: C17.1 R37.1
N01475: IC1.5 R29.1
N01481: D7.C Q3.B R25.1
N01489: D9.A D10.C R37.2
N01497: C15.2 D9.C Q3.C R25.2
N01519: R34.1 R35.2
N01523: R35.1 R36.2
N01527: R33.1 R34.2
N01535: IC1.1 R7.2 R36.1
N02374: D18.C R59.2 R61.1
N02384: IC2.11 R60.1
N02392: R53.1 R54.2
N02396: R54.1 R55.2
N02400: C21.2 IC2.1
N02406: IC2.7 R40.2
N02412: D18.A Q7.G R61.2 R64.2
N02424: IC2.15 R59.1
N02432: R39.1 R41.2
N02436: R41.1 R46.2
N02440: R46.1 R51.2
N02444: D19.C R63.1
N02448: D19.A D21.C R67.2 R69.2
N02460: C29.2 R69.1
N02498: D13.C R56.2
N02502: C25.2 D14.C IC2.16 R56.1
N02518: D16.A Q8.G R62.2 R65.2
N02530: IC2.4 R47.2
N02536: IC2.2 R43.2
N02550: D17.C Q6.B R66.1
N02568: D16.C R60.2 R62.1
N02610: C22.2 IC2.3 R44.2
N02620: IC2.6 R42.2 R49.2 R57.2
N02636: C23.2 IC2.5 R45.2 R51.1 R52.2
N02766: C28.2 D12.A IC2.9 R58.2 R63.2
N02786: C24.2 D12.C IC2.8 R49.1 R50.2
N03816: R91.1 R92.2
N03820: R85.1 R86.2
N03824: C38.2 R84.2
N03828: IC4.8 R97.2
N03836: Q10.4 R96.2 R97.1
N03848: IC3.8 R79.1
N03852: C45.2 CN2.1 CN2.2 L4.2
N03868: IC4.2 R88.2
N03874: IC4.3 R89.2
N03880: IC3.3 R72.2
N03886: IC3.2 R71.2
N03900: D20.A T2.5
N03904: D20.C R68.2
N03924: D23.C R81.1
N03928: R100.1 R101.2
N03932: D23.A PC3.A R83.2
N03940: C42.1 R95.2
N03944: PC4.A R93.1 R94.2
N03958: C42.2 IC5.1 PC4.CA R94.1
N03978: C34.2 C35.2 IC3.1 R74.1
N03994: C39.2 C40.2 IC4.1 R87.2
N04028: IC5.2 R95.1 R101.1 R102.2
N04044: C36.1 D22.C R75.1 R76.1
N04058: C37.1 D24.C R80.1 R82.1
N04078: C33.2 R70.2
N04082: Q9.4 R77.2 R79.2
N04252: C36.2 C37.2 C41.2 C43.2 C44.2 L4.1 R74.2 R75.2 R76.2 R80.2 R81.2 R82.2 R85.2 R87.1 R91.2 R93.2 R100.2 T2.9 T2.10
N04338: C38.1 D24.A IC4.5 Q10.5 Q10.6 Q10.7 Q10.8 T2.11 T2.12

Not connected (* = marked no-connect by the designer): IC2 13; T1 1 6 7 12; T2 2 4

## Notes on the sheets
sheet 1
- Vout = 24V 200W
sheet 3
- From Rectifier Diode
sheet 4
- Vac Input
- 100/240VAC
